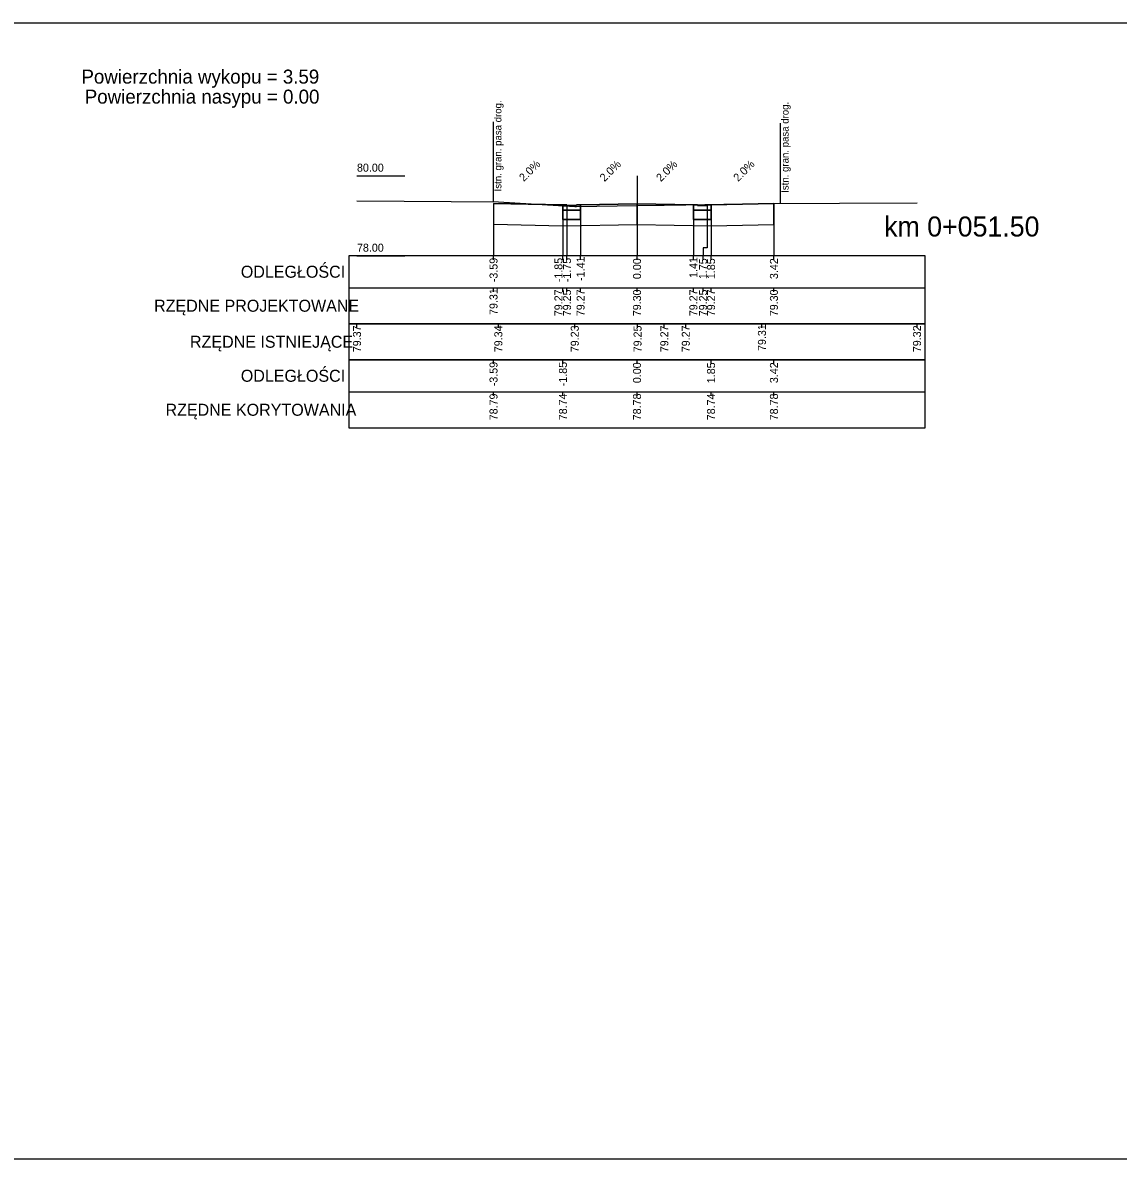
# Model space of a CAD drawing. Extents: x 7492871 to 7493499, y 5802964 to 5802992.
# Drawn here: x 7493329.51 to 7493356.9, y 5802963.88 to 5802992.28 of the extents above; entities that cross this region are included whole.
import ezdxf

# ---------------------------------------------------------------- set-up
doc = ezdxf.new("R2010")
doc.units = 0
for name, color, linetype in [('_wydruk', 7, 'Continuous'), ('d_pop_nasyp_opis', 7, 'Continuous'), ('d_pop_wykop_opis', 7, 'Continuous'), ('opisy_ramki_pop', 7, 'Continuous'), ('pop_comp_kostka', 7, 'Continuous'), ('pop_comp_lawa', 7, 'Continuous'), ('pop_comp_scieralna', 7, 'Continuous'), ('pop_granica_istn', 7, 'Continuous'), ('pop_opis', 7, 'Continuous'), ('pop_os', 7, 'Continuous'), ('pop_pikietaz', 7, 'Continuous'), ('pop_teren', 7, 'Continuous')]:
    doc.layers.add(name, color=color, linetype=linetype)

msp = doc.modelspace()

# ---------------------------------------------------------------- linework, layer by layer
msp.add_lwpolyline([(7493341.279, 5802987.766), (7493343.015, 5802987.731), (7493343.115, 5802987.731), (7493343.116, 5802987.711), (7493343.355, 5802987.711), (7493343.356, 5802987.731), (7493343.456, 5802987.731), (7493344.866, 5802987.759), (7493346.276, 5802987.731), (7493346.376, 5802987.731), (7493346.377, 5802987.711), (7493346.616, 5802987.711), (7493346.617, 5802987.731), (7493346.717, 5802987.731), (7493348.289, 5802987.762)])
at = {"layer": '_wydruk'}
msp.add_lwpolyline([(7492871.369, 5802992.281), (7493499.283, 5802992.281), (7493499.283, 5802963.881), (7492871.369, 5802963.881)], close=True, dxfattribs=at)
at = {"layer": 'opisy_ramki_pop'}
for points in [[(7493341.279, 5802987.246), (7493341.279, 5802986.659), (7493341.279, 5802986.659), (7493341.279, 5802986.459)], [(7493343.015, 5802987.202), (7493343.015, 5802986.659), (7493343.015, 5802986.659), (7493343.015, 5802986.459)], [(7493344.866, 5802987.239), (7493344.866, 5802986.659), (7493344.866, 5802986.659), (7493344.866, 5802986.459)], [(7493346.717, 5802987.202), (7493346.717, 5802986.659), (7493346.717, 5802986.659), (7493346.717, 5802986.459)], [(7493348.289, 5802987.242), (7493348.289, 5802986.659), (7493348.289, 5802986.659), (7493348.289, 5802986.459)]]:
    msp.add_lwpolyline(points, dxfattribs=at)
at = {"layer": 'pop_comp_kostka'}
for p, q in [((7493343.115, 5802987.731), (7493343.015, 5802987.731)), ((7493343.015, 5802987.731), (7493343.015, 5802987.601)), ((7493343.116, 5802987.711), (7493343.115, 5802987.731)), ((7493343.355, 5802987.711), (7493343.116, 5802987.711)), ((7493343.356, 5802987.731), (7493343.355, 5802987.711)), ((7493343.456, 5802987.731), (7493343.356, 5802987.731)), ((7493343.456, 5802987.601), (7493343.456, 5802987.731)), ((7493346.376, 5802987.731), (7493346.276, 5802987.731)), ((7493346.276, 5802987.731), (7493346.276, 5802987.601)), ((7493346.377, 5802987.711), (7493346.376, 5802987.731)), ((7493346.616, 5802987.711), (7493346.377, 5802987.711)), ((7493346.617, 5802987.731), (7493346.616, 5802987.711)), ((7493346.717, 5802987.731), (7493346.617, 5802987.731)), ((7493346.717, 5802987.601), (7493346.717, 5802987.731)), ((7493343.015, 5802987.601), (7493343.456, 5802987.601)), ((7493346.276, 5802987.601), (7493346.717, 5802987.601))]:
    msp.add_line(p, q, dxfattribs=at)
at = {"layer": 'pop_comp_lawa'}
for p, q in [((7493343.456, 5802987.601), (7493343.015, 5802987.601)), ((7493343.015, 5802987.601), (7493343.015, 5802987.361)), ((7493343.015, 5802987.361), (7493343.456, 5802987.361)), ((7493343.456, 5802987.361), (7493343.456, 5802987.601)), ((7493346.717, 5802987.601), (7493346.276, 5802987.601)), ((7493346.276, 5802987.601), (7493346.276, 5802987.361)), ((7493346.276, 5802987.361), (7493346.717, 5802987.361)), ((7493346.717, 5802987.361), (7493346.717, 5802987.601))]:
    msp.add_line(p, q, dxfattribs=at)
at = {"layer": 'pop_comp_scieralna'}
for p, q in [((7493343.015, 5802987.731), (7493341.279, 5802987.766)), ((7493341.279, 5802987.766), (7493341.279, 5802987.246)), ((7493343.015, 5802987.361), (7493343.015, 5802987.731)), ((7493344.866, 5802987.759), (7493343.456, 5802987.731)), ((7493343.456, 5802987.731), (7493343.456, 5802987.361)), ((7493344.866, 5802987.239), (7493344.866, 5802987.759)), ((7493346.276, 5802987.731), (7493344.866, 5802987.759)), ((7493344.866, 5802987.759), (7493344.866, 5802987.239)), ((7493346.276, 5802987.361), (7493346.276, 5802987.731)), ((7493348.289, 5802987.762), (7493346.717, 5802987.731)), ((7493346.717, 5802987.731), (7493346.717, 5802987.361)), ((7493348.289, 5802987.242), (7493348.289, 5802987.762)), ((7493343.456, 5802987.361), (7493343.015, 5802987.361)), ((7493346.717, 5802987.361), (7493346.276, 5802987.361)), ((7493341.279, 5802987.246), (7493343.015, 5802987.202)), ((7493343.015, 5802987.202), (7493344.866, 5802987.239)), ((7493344.866, 5802987.239), (7493346.717, 5802987.202)), ((7493346.717, 5802987.202), (7493348.289, 5802987.242))]:
    msp.add_line(p, q, dxfattribs=at)
at = {"layer": 'pop_granica_istn'}
for p, q in [((7493341.279, 5802988.305), (7493341.279, 5802989.805)), ((7493348.457, 5802988.269), (7493348.457, 5802989.769)), ((7493341.279, 5802987.805), (7493341.279, 5802988.305)), ((7493348.457, 5802987.769), (7493348.457, 5802988.269))]:
    msp.add_line(p, q, dxfattribs=at)
at = {"layer": 'pop_opis'}
for p, q in [((7493337.866, 5802988.459), (7493339.066, 5802988.459)), ((7493337.666, 5802986.459), (7493337.666, 5802984.759)), ((7493337.666, 5802986.459), (7493337.666, 5802984.759)), ((7493337.666, 5802986.459), (7493337.666, 5802984.759)), ((7493337.666, 5802986.459), (7493337.666, 5802984.759)), ((7493337.866, 5802986.459), (7493339.066, 5802986.459)), ((7493341.279, 5802986.359), (7493341.279, 5802986.459)), ((7493343.015, 5802986.359), (7493343.015, 5802986.459)), ((7493343.116, 5802986.359), (7493343.116, 5802986.459)), ((7493343.456, 5802986.359), (7493343.456, 5802986.459)), ((7493344.866, 5802986.359), (7493344.866, 5802986.459)), ((7493346.276, 5802986.359), (7493346.276, 5802986.459)), ((7493346.517, 5802986.359), (7493346.517, 5802986.459)), ((7493346.717, 5802986.359), (7493346.717, 5802986.459)), ((7493348.289, 5802986.359), (7493348.289, 5802986.459)), ((7493337.666, 5802985.659), (7493352.066, 5802985.659)), ((7493337.666, 5802985.659), (7493352.066, 5802985.659)), ((7493337.666, 5802985.659), (7493352.066, 5802985.659)), ((7493337.666, 5802985.659), (7493352.066, 5802985.659)), ((7493341.279, 5802985.559), (7493341.279, 5802985.659)), ((7493343.015, 5802985.559), (7493343.015, 5802985.659)), ((7493343.116, 5802985.559), (7493343.116, 5802985.659)), ((7493343.456, 5802985.559), (7493343.456, 5802985.659)), ((7493344.866, 5802985.559), (7493344.866, 5802985.659)), ((7493346.276, 5802985.559), (7493346.276, 5802985.659)), ((7493346.517, 5802985.559), (7493346.517, 5802985.659)), ((7493346.717, 5802985.559), (7493346.717, 5802985.659)), ((7493348.289, 5802985.559), (7493348.289, 5802985.659)), ((7493337.666, 5802984.759), (7493337.666, 5802983.859)), ((7493337.866, 5802984.659), (7493337.866, 5802984.759)), ((7493341.4, 5802984.659), (7493341.4, 5802984.759)), ((7493343.31, 5802984.659), (7493343.31, 5802984.759)), ((7493344.88, 5802984.659), (7493344.88, 5802984.759)), ((7493345.549, 5802984.659), (7493345.549, 5802984.759)), ((7493346.085, 5802984.659), (7493346.085, 5802984.759)), ((7493347.989, 5802984.659), (7493347.989, 5802984.759)), ((7493351.866, 5802984.659), (7493351.866, 5802984.759)), ((7493337.666, 5802983.859), (7493337.666, 5802982.159)), ((7493341.279, 5802983.759), (7493341.279, 5802983.859)), ((7493343.015, 5802983.759), (7493343.015, 5802983.859)), ((7493344.866, 5802983.759), (7493344.866, 5802983.859)), ((7493346.717, 5802983.759), (7493346.717, 5802983.859)), ((7493348.289, 5802983.759), (7493348.289, 5802983.859)), ((7493337.666, 5802983.059), (7493352.066, 5802983.059)), ((7493341.279, 5802982.959), (7493341.279, 5802983.059)), ((7493343.015, 5802982.959), (7493343.015, 5802983.059)), ((7493344.866, 5802982.959), (7493344.866, 5802983.059)), ((7493346.717, 5802982.959), (7493346.717, 5802983.059)), ((7493348.289, 5802982.959), (7493348.289, 5802983.059))]:
    msp.add_line(p, q, dxfattribs=at)
for points in [[(7493341.279, 5802987.766), (7493341.279, 5802986.659), (7493341.279, 5802986.659), (7493341.279, 5802986.459)], [(7493343.015, 5802987.731), (7493343.015, 5802986.659), (7493343.015, 5802986.659), (7493343.015, 5802986.459)], [(7493343.116, 5802987.711), (7493343.116, 5802986.659), (7493343.116, 5802986.659), (7493343.116, 5802986.459)], [(7493343.456, 5802987.731), (7493343.456, 5802986.659), (7493343.456, 5802986.659), (7493343.456, 5802986.459)], [(7493344.866, 5802987.759), (7493344.866, 5802986.659), (7493344.866, 5802986.659), (7493344.866, 5802986.459)], [(7493346.276, 5802987.731), (7493346.276, 5802986.659), (7493346.276, 5802986.659), (7493346.276, 5802986.459)], [(7493346.616, 5802987.711), (7493346.616, 5802986.659), (7493346.517, 5802986.659), (7493346.517, 5802986.459)], [(7493346.717, 5802987.731), (7493346.717, 5802986.659), (7493346.717, 5802986.659), (7493346.717, 5802986.459)], [(7493348.289, 5802987.762), (7493348.289, 5802986.659), (7493348.289, 5802986.659), (7493348.289, 5802986.459)]]:
    msp.add_lwpolyline(points, dxfattribs=at)
for points in [[(7493337.666, 5802986.459), (7493337.666, 5802984.759), (7493352.066, 5802984.759), (7493352.066, 5802986.459)], [(7493337.666, 5802986.459), (7493337.666, 5802984.759), (7493352.066, 5802984.759), (7493352.066, 5802986.459)], [(7493337.666, 5802986.459), (7493337.666, 5802984.759), (7493352.066, 5802984.759), (7493352.066, 5802986.459)], [(7493337.666, 5802986.459), (7493337.666, 5802984.759), (7493352.066, 5802984.759), (7493352.066, 5802986.459)], [(7493337.666, 5802984.759), (7493337.666, 5802983.859), (7493352.066, 5802983.859), (7493352.066, 5802984.759)], [(7493337.666, 5802983.859), (7493337.666, 5802982.159), (7493352.066, 5802982.159), (7493352.066, 5802983.859)]]:
    msp.add_lwpolyline(points, close=True, dxfattribs=at)
at = {"layer": 'pop_os'}
msp.add_line((7493344.866, 5802988.459), (7493344.866, 5802986.459), dxfattribs=at)
at = {"layer": 'pop_teren'}
msp.add_lwpolyline([(7493337.866, 5802987.827), (7493341.4, 5802987.803), (7493343.31, 5802987.688), (7493343.354, 5802987.688), (7493344.88, 5802987.711), (7493345.549, 5802987.726), (7493346.085, 5802987.732), (7493347.989, 5802987.765), (7493351.866, 5802987.782)], dxfattribs=at)

# ---------------------------------------------------------------- texts
at = {"layer": 'd_pop_nasyp_opis'}
msp.add_text('Powierzchnia nasypu = 0.00', height=0.35, dxfattribs=at).set_placement((7493331.061, 5802990.259))
at = {"layer": 'd_pop_wykop_opis'}
msp.add_text('Powierzchnia wykopu = 3.59', height=0.35, dxfattribs=at).set_placement((7493330.978, 5802990.759))
at = {"layer": 'pop_granica_istn'}
for p in [(7493341.477, 5802988.066), (7493348.655, 5802988.03)]:
    msp.add_text('Istn. gran. pasa drog.', height=0.18, rotation=90, dxfattribs=at).set_placement(p)
at = {"layer": 'pop_opis'}
for s, height, p in [('80.00', 0.2, (7493337.866, 5802988.559)), ('78.00', 0.2, (7493337.866, 5802986.559)), ('ODLEGŁOŚCI', 0.3, (7493334.962, 5802985.909)), ('ODLEGŁOŚCI', 0.3, (7493334.962, 5802985.909)), ('ODLEGŁOŚCI', 0.3, (7493334.962, 5802985.909)), ('ODLEGŁOŚCI', 0.3, (7493334.962, 5802985.909)), ('RZĘDNE PROJEKTOWANE', 0.3, (7493332.794, 5802985.059)), ('RZĘDNE PROJEKTOWANE', 0.3, (7493332.794, 5802985.059)), ('RZĘDNE PROJEKTOWANE', 0.3, (7493332.794, 5802985.059)), ('RZĘDNE PROJEKTOWANE', 0.3, (7493332.794, 5802985.059)), ('RZĘDNE ISTNIEJĄCE', 0.3, (7493333.691, 5802984.159)), ('ODLEGŁOŚCI', 0.3, (7493334.962, 5802983.309)), ('RZĘDNE KORYTOWANIA', 0.3, (7493333.08, 5802982.459))]:
    msp.add_text(s, height=height, dxfattribs=at).set_placement(p)
for s, rotation, p in [('2.0%', 45, (7493342.038, 5802988.298)), ('2.0%', 45, (7493344.053, 5802988.295)), ('2.0%', 45, (7493345.463, 5802988.295)), ('2.0%', 45, (7493347.394, 5802988.297)), ('-3.59', 90, (7493341.379, 5802985.797)), ('-1.85', 90, (7493343.002, 5802985.796)), ('-1.75', 90, (7493343.216, 5802985.796)), ('-1.41', 90, (7493343.556, 5802985.829)), ('0.00', 90, (7493344.966, 5802985.874)), ('1.41', 90, (7493346.376, 5802985.905)), ('1.75', 90, (7493346.617, 5802985.873)), ('1.85', 90, (7493346.817, 5802985.873)), ('3.42', 90, (7493348.389, 5802985.875)), ('79.31', 90, (7493341.379, 5802984.978)), ('79.27', 90, (7493343.002, 5802984.947)), ('79.25', 90, (7493343.216, 5802984.945)), ('79.27', 90, (7493343.556, 5802984.947)), ('79.30', 90, (7493344.966, 5802984.947)), ('79.27', 90, (7493346.376, 5802984.947)), ('79.25', 90, (7493346.617, 5802984.945)), ('79.27', 90, (7493346.817, 5802984.947)), ('79.30', 90, (7493348.389, 5802984.947)), ('79.37', 90, (7493337.966, 5802984.047)), ('79.34', 90, (7493341.5, 5802984.047)), ('79.23', 90, (7493343.41, 5802984.047)), ('79.25', 90, (7493344.98, 5802984.045)), ('79.27', 90, (7493345.649, 5802984.047)), ('79.27', 90, (7493346.185, 5802984.047)), ('79.31', 90, (7493348.089, 5802984.078)), ('79.32', 90, (7493351.966, 5802984.048)), ('-3.59', 90, (7493341.379, 5802983.197)), ('-1.85', 90, (7493343.115, 5802983.196)), ('0.00', 90, (7493344.966, 5802983.274)), ('1.85', 90, (7493346.817, 5802983.273)), ('3.42', 90, (7493348.389, 5802983.275)), ('78.79', 90, (7493341.379, 5802982.346)), ('78.74', 90, (7493343.115, 5802982.347)), ('78.78', 90, (7493344.966, 5802982.346)), ('78.74', 90, (7493346.817, 5802982.347)), ('78.78', 90, (7493348.389, 5802982.346))]:
    msp.add_text(s, height=0.2, rotation=rotation, dxfattribs=at).set_placement(p)
at = {"layer": 'pop_pikietaz'}
msp.add_text('km 0+051.50', height=0.5, dxfattribs=at).set_placement((7493351.043, 5802986.939))

doc.saveas('drawing.dxf')
